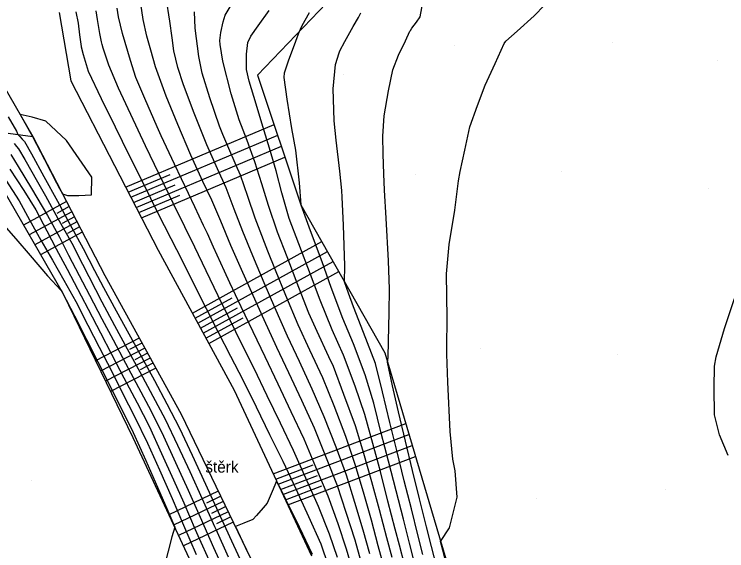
# Model space of a CAD drawing. Extents: x -448957 to -448612, y -1107690 to -1107245.
# Drawn here: x -448752.23 to -448714.86, y -1107411.41 to -1107383.27 of the extents above; entities that cross this region are included whole.
import ezdxf

# ---------------------------------------------------------------- set-up
doc = ezdxf.new("R2010")
doc.units = 0
for name, color, linetype in [('Default', 7, 'Continuous'), ('Vrstva 1', 7, 'Continuous'), ('Vrstva 11', 7, 'Continuous'), ('Vrstva 14', 7, 'Continuous'), ('Vrstva 15', 7, 'Continuous'), ('Vrstva 16', 7, 'Continuous'), ('Vrstva 17', 7, 'Continuous'), ('Vrstva 40', 7, 'Continuous')]:
    doc.layers.add(name, color=color, linetype=linetype)

# ---------------------------------------------------------------- blocks, each defined once
blk = doc.blocks.new('POINT_DISPLAY')
at = {"layer": 'Default'}
blk.add_line((0, 0), (0, 0), dxfattribs=at)

msp = doc.modelspace()

# ---------------------------------------------------------------- linework, layer by layer
at = {"layer": 'Vrstva 11'}
for p, q in [((-448749.871, -1107383.186), (-448749.267, -1107386.764)), ((-448753.87, -1107385.167), (-448751.25, -1107389.68)), ((-448749.267, -1107386.764), (-448744.681, -1107395.638)), ((-448751.25, -1107389.68), (-448747.484, -1107396.982)), ((-448744.681, -1107395.638), (-448740.7, -1107402.99)), ((-448747.484, -1107396.982), (-448743.482, -1107404.246)), ((-448740.7, -1107402.99), (-448736.632, -1107411.673)), ((-448743.482, -1107404.246), (-448739.337, -1107412.816))]:
    msp.add_line(p, q, dxfattribs=at)
at = {"layer": 'Vrstva 14'}
for p, q in [((-448735.861, -1107382.696), (-448739.463, -1107386.469)), ((-448739.463, -1107386.469), (-448737.194, -1107393.26)), ((-448752.54, -1107389.502), (-448751.25, -1107389.68)), ((-448753.315, -1107391.608), (-448749.664, -1107397.93)), ((-448737.194, -1107393.26), (-448732.795, -1107401.025)), ((-448749.664, -1107397.93), (-448746.015, -1107405.477)), ((-448732.795, -1107401.025), (-448730.205, -1107409.781)), ((-448746.015, -1107405.477), (-448742.15, -1107413.742)), ((-448730.205, -1107409.781), (-448728.39, -1107415.928))]:
    msp.add_line(p, q, dxfattribs=at)
at = {"layer": 'Vrstva 15'}
for p, q in [((-448746.386, -1107392.338), (-448738.601, -1107389.049)), ((-448746.11, -1107392.873), (-448738.41, -1107389.62)), ((-448745.834, -1107393.408), (-448738.219, -1107390.191)), ((-448745.557, -1107393.942), (-448738.029, -1107390.762)), ((-448746.248, -1107392.606), (-448744.048, -1107391.676)), ((-448745.972, -1107393.14), (-448743.796, -1107392.221)), ((-448745.695, -1107393.675), (-448743.544, -1107392.766)), ((-448749.487, -1107393.098), (-448751.743, -1107394.33)), ((-448749.35, -1107393.364), (-448749.994, -1107393.716)), ((-448749.212, -1107393.631), (-448751.443, -1107394.849)), ((-448749.075, -1107393.898), (-448749.712, -1107394.246)), ((-448748.937, -1107394.164), (-448751.143, -1107395.369)), ((-448748.8, -1107394.431), (-448749.43, -1107394.775)), ((-448748.662, -1107394.698), (-448750.843, -1107395.889)), ((-448742.887, -1107398.952), (-448736.1, -1107395.192)), ((-448742.601, -1107399.479), (-448735.804, -1107395.714)), ((-448742.315, -1107400.007), (-448735.508, -1107396.236)), ((-448742.03, -1107400.534), (-448735.212, -1107396.758)), ((-448742.744, -1107399.215), (-448740.802, -1107398.14)), ((-448742.458, -1107399.743), (-448740.513, -1107398.666)), ((-448742.172, -1107400.271), (-448740.225, -1107399.192)), ((-448745.676, -1107400.263), (-448747.964, -1107401.446)), ((-448745.531, -1107400.526), (-448746.185, -1107400.864)), ((-448745.387, -1107400.789), (-448747.703, -1107401.986)), ((-448745.097, -1107401.315), (-448747.442, -1107402.526)), ((-448745.242, -1107401.052), (-448745.904, -1107401.394)), ((-448744.952, -1107401.578), (-448745.622, -1107401.924)), ((-448744.807, -1107401.84), (-448747.18, -1107403.067)), ((-448738.645, -1107407.377), (-448731.696, -1107404.739)), ((-448738.389, -1107407.922), (-448731.526, -1107405.316)), ((-448738.134, -1107408.467), (-448731.355, -1107405.893)), ((-448737.879, -1107409.012), (-448731.184, -1107406.47)), ((-448738.517, -1107407.65), (-448736.556, -1107406.905)), ((-448738.262, -1107408.194), (-448736.325, -1107407.459)), ((-448738.006, -1107408.739), (-448736.094, -1107408.013)), ((-448741.527, -1107408.289), (-448744.123, -1107409.524)), ((-448741.265, -1107408.829), (-448743.868, -1107410.067)), ((-448741.396, -1107408.559), (-448742.138, -1107408.912)), ((-448741.135, -1107409.099), (-448741.878, -1107409.453)), ((-448741.004, -1107409.369), (-448743.614, -1107410.611)), ((-448740.743, -1107409.909), (-448743.36, -1107411.154)), ((-448740.873, -1107409.639), (-448741.619, -1107409.994))]:
    msp.add_line(p, q, dxfattribs=at)
at = {"layer": 'Vrstva 16'}
for points in [[(-448734.507, -1107412.352), (-448734.804, -1107411.331), (-448735.241, -1107410.005), (-448735.762, -1107408.559), (-448736.409, -1107407.026), (-448737.025, -1107405.563), (-448737.707, -1107404.126), (-448738.39, -1107402.68), (-448739.074, -1107401.249), (-448739.704, -1107399.937), (-448740.333, -1107398.615), (-448740.921, -1107397.365), (-448741.204, -1107396.749), (-448741.775, -1107395.494), (-448742.1, -1107394.768), (-448742.296, -1107394.349), (-448742.763, -1107393.373), (-448743.096, -1107392.679), (-448743.825, -1107391.138), (-448744.523, -1107389.657), (-448744.735, -1107389.179), (-448745.38, -1107387.697), (-448745.849, -1107386.584), (-448746.126, -1107385.705), (-448746.547, -1107384.28), (-448746.763, -1107383.405), (-448746.835, -1107382.953)], [(-448731.763, -1107412.142), (-448732.03, -1107411.112), (-448732.244, -1107410.281), (-448732.628, -1107408.808), (-448733.028, -1107407.262), (-448733.43, -1107405.793), (-448733.839, -1107404.271), (-448734.352, -1107402.789), (-448734.962, -1107401.155), (-448735.548, -1107399.824), (-448736.19, -1107398.278), (-448736.694, -1107396.926), (-448737.309, -1107395.307), (-448737.805, -1107393.981), (-448738.189, -1107392.641), (-448738.49, -1107391.484), (-448738.834, -1107390.294), (-448739.184, -1107389.153), (-448739.546, -1107387.993), (-448739.903, -1107386.777), (-448740.047, -1107386.171), (-448740.049, -1107385.374), (-448739.978, -1107384.754), (-448739.822, -1107384.425), (-448739.433, -1107383.881), (-448738.852, -1107383.068)], [(-448752.407, -1107390.621), (-448752.021, -1107391.261), (-448751.318, -1107392.407), (-448750.478, -1107393.82), (-448749.85, -1107394.973), (-448749.377, -1107395.902), (-448748.816, -1107396.977), (-448748.277, -1107398.001), (-448747.629, -1107399.241), (-448747.047, -1107400.352), (-448746.391, -1107401.575), (-448745.715, -1107402.842), (-448745.072, -1107404.065), (-448744.404, -1107405.406), (-448743.766, -1107406.787), (-448743.113, -1107408.229), (-448742.485, -1107409.65), (-448741.77, -1107411.251), (-448741.121, -1107412.693)], [(-448714.797, -1107406.413), (-448715.24, -1107405.328), (-448715.513, -1107404.285), (-448715.528, -1107402.873), (-448715.506, -1107401.726), (-448715.424, -1107401.238), (-448714.977, -1107399.759), (-448714.452, -1107398.185)]]:
    msp.add_lwpolyline(points, dxfattribs=at)
at = {"layer": 'Vrstva 17'}
for points in [[(-448733.584, -1107411.573), (-448733.922, -1107410.334), (-448734.365, -1107408.878), (-448734.809, -1107407.451), (-448735.345, -1107405.984), (-448735.971, -1107404.394), (-448736.598, -1107402.934), (-448737.274, -1107401.482), (-448737.895, -1107400.16), (-448738.555, -1107398.662), (-448739.117, -1107397.36), (-448739.712, -1107395.946), (-448740.235, -1107394.676), (-448740.689, -1107393.492), (-448741.121, -1107392.377), (-448741.571, -1107391.372), (-448742.13, -1107390.126), (-448742.788, -1107388.459), (-448743.346, -1107386.974), (-448743.648, -1107386.068), (-448743.856, -1107385.186), (-448743.951, -1107384.517), (-448744.071, -1107383.633), (-448744.26, -1107382.388)], [(-448730.074, -1107412.274), (-448730.348, -1107411.198), (-448730.607, -1107410.162), (-448730.975, -1107408.684), (-448731.344, -1107407.206), (-448732.085, -1107404.133), (-448732.385, -1107402.761), (-448732.648, -1107401.522), (-448732.621, -1107401.269), (-448732.594, -1107400.426), (-448732.57, -1107398.909), (-448732.555, -1107397.684), (-448732.608, -1107396.21), (-448732.732, -1107393.966), (-448732.81, -1107392.499), (-448732.841, -1107391.647), (-448732.88, -1107390.617), (-448732.906, -1107389.663), (-448732.82, -1107388.6), (-448732.609, -1107387.282), (-448732.367, -1107386.179), (-448732.08, -1107385.419), (-448731.714, -1107384.662), (-448731.48, -1107384.164), (-448731.451, -1107384.124), (-448731.37, -1107384.005), (-448731.131, -1107383.695), (-448730.947, -1107383.409), (-448730.794, -1107382.647)], [(-448734.033, -1107411.994), (-448734.347, -1107410.865), (-448734.813, -1107409.415), (-448735.267, -1107408.017), (-448735.854, -1107406.55), (-448736.488, -1107404.979), (-448737.15, -1107403.528), (-448737.828, -1107402.079), (-448738.455, -1107400.759), (-448739.128, -1107399.299), (-448739.705, -1107398.027), (-448740.316, -1107396.657), (-448740.864, -1107395.395), (-448741.395, -1107394.13), (-448741.869, -1107393.029), (-448742.33, -1107392.042), (-448742.964, -1107390.666), (-448743.657, -1107389.06), (-448744.258, -1107387.576), (-448744.825, -1107386.027), (-448745.071, -1107385.147), (-448745.278, -1107384.421), (-448745.47, -1107383.539), (-448745.595, -1107382.733)], [(-448732.415, -1107411.759), (-448732.686, -1107410.73), (-448733.071, -1107409.273), (-448733.47, -1107407.804), (-448733.893, -1107406.32), (-448734.325, -1107404.853), (-448734.938, -1107403.225), (-448735.493, -1107401.748), (-448735.726, -1107401.243), (-448736.336, -1107399.918), (-448736.771, -1107398.948), (-448737.299, -1107397.602), (-448737.922, -1107396.003), (-448738.42, -1107394.705), (-448738.893, -1107393.303), (-448739.237, -1107392.16), (-448739.602, -1107391.006), (-448740.017, -1107389.886), (-448740.424, -1107388.805), (-448740.86, -1107387.446), (-448741.288, -1107385.735), (-448741.42, -1107384.852), (-448741.448, -1107384.642), (-448741.387, -1107384.233), (-448741.263, -1107383.664), (-448741.159, -1107383.321), (-448740.9, -1107382.883)], [(-448729.635, -1107411.863), (-448729.754, -1107411.382), (-448729.868, -1107410.922), (-448729.404, -1107410.219), (-448728.997, -1107408.604), (-448729.107, -1107407.219), (-448729.231, -1107406.603), (-448729.361, -1107405.15), (-448729.489, -1107402.573), (-448729.544, -1107401.099), (-448729.539, -1107400.752), (-448729.532, -1107399.205), (-448729.553, -1107396.891), (-448729.423, -1107395.348), (-448729.13, -1107393.554), (-448728.923, -1107392.017), (-448728.84, -1107391.528), (-448728.606, -1107390.4), (-448728.332, -1107389.184), (-448727.927, -1107388.052), (-448727.525, -1107386.99), (-448727.013, -1107385.855), (-448726.528, -1107384.805), (-448726.45, -1107384.68), (-448725.853, -1107384.166), (-448724.959, -1107383.349), (-448724.428, -1107382.793)], [(-448735.751, -1107412.198), (-448736.133, -1107411.074), (-448736.772, -1107409.632), (-448737.447, -1107408.178), (-448738.133, -1107406.733), (-448738.827, -1107405.329), (-448739.527, -1107403.887), (-448740.217, -1107402.473), (-448740.868, -1107401.221), (-448741.52, -1107399.963), (-448742.147, -1107398.726), (-448742.789, -1107397.443), (-448743.412, -1107396.205), (-448744.004, -1107395.047), (-448744.689, -1107393.686), (-448745.439, -1107392.182), (-448746.181, -1107390.702), (-448746.924, -1107389.186), (-448747.656, -1107387.706), (-448748.327, -1107386.274), (-448748.592, -1107385.405), (-448748.697, -1107384.993), (-448748.7, -1107384.966), (-448748.782, -1107384.355), (-448748.864, -1107383.741), (-448748.972, -1107383.15)], [(-448735.278, -1107411.764), (-448735.687, -1107410.539), (-448736.267, -1107409.095), (-448736.928, -1107407.602), (-448737.579, -1107406.148), (-448738.267, -1107404.727), (-448738.959, -1107403.284), (-448739.645, -1107401.861), (-448740.286, -1107400.579), (-448740.926, -1107399.289), (-448741.534, -1107398.046), (-448742.164, -1107396.728), (-448742.759, -1107395.481), (-448743.284, -1107394.419), (-448743.893, -1107393.182), (-448744.632, -1107391.66), (-448745.352, -1107390.179), (-448746.762, -1107387.145), (-448747.263, -1107385.937), (-448747.566, -1107385.059), (-448747.624, -1107384.865), (-448747.659, -1107384.719), (-448747.736, -1107384.274), (-448747.855, -1107383.554), (-448747.925, -1107383.1)], [(-448732.859, -1107412.178), (-448733.135, -1107411.152), (-448733.497, -1107409.804), (-448733.917, -1107408.341), (-448734.351, -1107406.886), (-448734.835, -1107405.419), (-448735.455, -1107403.81), (-448736.045, -1107402.341), (-448736.72, -1107400.885), (-448737.336, -1107399.561), (-448737.981, -1107398.024), (-448738.528, -1107396.692), (-448738.924, -1107395.706), (-448739.424, -1107394.429), (-448739.596, -1107393.965), (-448739.984, -1107392.836), (-448740.37, -1107391.719), (-448740.59, -1107391.206), (-448741.034, -1107390.19), (-448741.297, -1107389.586), (-448741.46, -1107389.145), (-448741.973, -1107387.659), (-448742.376, -1107386.363), (-448742.544, -1107385.48), (-448742.741, -1107384.008), (-448742.778, -1107383.14)], [(-448731.236, -1107412.039), (-448731.501, -1107411.008), (-448731.821, -1107409.749), (-448732.2, -1107408.274), (-448732.595, -1107406.712), (-448732.981, -1107405.24), (-448733.374, -1107403.673), (-448733.82, -1107402.187), (-448734.434, -1107400.562), (-448734.991, -1107399.224), (-448735.609, -1107397.608), (-448736.088, -1107396.25), (-448736.691, -1107394.624), (-448737.182, -1107393.282), (-448737.183, -1107393.269), (-448737.274, -1107392.113), (-448737.463, -1107390.399), (-448737.666, -1107389.265), (-448737.909, -1107387.719), (-448738.077, -1107386.585), (-448738.061, -1107386.349), (-448737.837, -1107385.723), (-448737.46, -1107384.686), (-448737.264, -1107384.166), (-448737.216, -1107384.049), (-448737.124, -1107383.86), (-448736.744, -1107383.187)], [(-448730.792, -1107411.618), (-448731.054, -1107410.585), (-448731.398, -1107409.216), (-448731.772, -1107407.74), (-448732.161, -1107406.163), (-448732.533, -1107404.686), (-448732.91, -1107403.075), (-448733.289, -1107401.585), (-448733.906, -1107399.969), (-448734.435, -1107398.624), (-448734.698, -1107397.902), (-448734.901, -1107397.308), (-448734.893, -1107396.467), (-448734.955, -1107394.334), (-448735.031, -1107392.866), (-448735.056, -1107392.519), (-448735.157, -1107391.506), (-448735.34, -1107389.877), (-448735.449, -1107388.865), (-448735.462, -1107388.291), (-448735.496, -1107387.189), (-448735.375, -1107385.907), (-448735.196, -1107385.299), (-448735.155, -1107385.185), (-448734.887, -1107384.699), (-448734.45, -1107383.922), (-448734.18, -1107383.437), (-448734.057, -1107383.198)], [(-448752.552, -1107388.661), (-448752.118, -1107389.413), (-448752.032, -1107389.572), (-448751.943, -1107389.677), (-448751.814, -1107389.829), (-448751.697, -1107389.95), (-448751.33, -1107390.588), (-448750.68, -1107391.784), (-448749.963, -1107393.084), (-448749.311, -1107394.278), (-448748.62, -1107395.554), (-448748.015, -1107396.711), (-448747.549, -1107397.609), (-448746.884, -1107398.829), (-448746.217, -1107400.038), (-448745.552, -1107401.25), (-448744.881, -1107402.486), (-448744.225, -1107403.701), (-448743.566, -1107404.99), (-448742.903, -1107406.4), (-448742.198, -1107407.928), (-448741.539, -1107409.367), (-448740.835, -1107410.893), (-448740.17, -1107412.33)], [(-448749.428, -1107392.781), (-448748.844, -1107392.783), (-448748.177, -1107392.741), (-448748.165, -1107391.819), (-448749.49, -1107389.891), (-448750.567, -1107388.872), (-448751.287, -1107388.674), (-448751.915, -1107388.535), (-448751.267, -1107389.678), (-448751.262, -1107389.682), (-448750.639, -1107390.889), (-448750.011, -1107392.106), (-448749.85, -1107392.406), (-448749.698, -1107392.69), (-448749.428, -1107392.781)], [(-448752.238, -1107390.06), (-448752.111, -1107390.208), (-448752.002, -1107390.337), (-448751.676, -1107390.893), (-448751.004, -1107392.069), (-448750.592, -1107392.798), (-448749.933, -1107393.985), (-448749.214, -1107395.287), (-448748.65, -1107396.387), (-448747.626, -1107398.359), (-448746.97, -1107399.593), (-448746.3, -1107400.82), (-448745.638, -1107402.033), (-448744.961, -1107403.3), (-448744.312, -1107404.519), (-448743.666, -1107405.881), (-448743.018, -1107407.263), (-448742.374, -1107408.691), (-448741.726, -1107410.134), (-448741.658, -1107410.285), (-448741.001, -1107411.725)], [(-448752.466, -1107391.394), (-448751.729, -1107392.509), (-448751.09, -1107393.532), (-448750.511, -1107394.633), (-448750.028, -1107395.571), (-448749.452, -1107396.639), (-448748.346, -1107398.739), (-448747.706, -1107399.983), (-448747.121, -1107401.108), (-448746.473, -1107402.345), (-448745.788, -1107403.66), (-448745.153, -1107404.887), (-448744.498, -1107406.307), (-448743.868, -1107407.692), (-448743.338, -1107408.905), (-448742.732, -1107410.302), (-448742.597, -1107410.613), (-448741.954, -1107412.056)], [(-448752.677, -1107391.98), (-448751.975, -1107393.051), (-448751.422, -1107394.053), (-448750.834, -1107395.115), (-448750.228, -1107396.166), (-448749.625, -1107397.222), (-448749.004, -1107398.338), (-448748.366, -1107399.583), (-448747.776, -1107400.738), (-448747.136, -1107401.982), (-448746.544, -1107403.144), (-448745.917, -1107404.38), (-448745.239, -1107405.775), (-448744.616, -1107407.163), (-448743.954, -1107408.668), (-448743.354, -1107410.067), (-448742.687, -1107411.611)], [(-448753.168, -1107393.902), (-448752.149, -1107395.05), (-448751.401, -1107395.934), (-448750.479, -1107396.989), (-448749.759, -1107397.766), (-448749.71, -1107397.847), (-448749.072, -1107399.084), (-448748.437, -1107400.33), (-448747.844, -1107401.497), (-448747.21, -1107402.743), (-448745.991, -1107405.211), (-448745.326, -1107406.683), (-448744.71, -1107408.074), (-448744.234, -1107409.191), (-448743.814, -1107410.184), (-448743.957, -1107410.69), (-448744.341, -1107412.183), (-448744.778, -1107413.902), (-448745.203, -1107415.494), (-448745.497, -1107416.608), (-448745.747, -1107417.444), (-448746.06, -1107418.563), (-448746.271, -1107419.421), (-448746.351, -1107419.743)], [(-448736.579, -1107411.609), (-448737.276, -1107410.168), (-448737.966, -1107408.755), (-448738.22, -1107408.247), (-448738.467, -1107407.755), (-448738.699, -1107408.313), (-448738.957, -1107408.915), (-448739.174, -1107409.159), (-448739.527, -1107409.557), (-448739.723, -1107409.781), (-448740.194, -1107409.972), (-448740.633, -1107410.136), (-448740.003, -1107411.482)]]:
    msp.add_lwpolyline(points, dxfattribs=at)

# ---------------------------------------------------------------- block references
at = {"layer": 'Vrstva 1', "xscale": 0.1, "yscale": 0.10000000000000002}
for p in [(-448749.267, -1107386.764), (-448739.463, -1107386.469), (-448751.25, -1107389.68), (-448751.25, -1107389.68), (-448737.194, -1107393.26), (-448744.681, -1107395.638), (-448747.484, -1107396.982), (-448749.664, -1107397.93), (-448732.795, -1107401.025), (-448740.7, -1107402.99), (-448743.482, -1107404.246), (-448746.015, -1107405.477), (-448730.205, -1107409.781)]:
    msp.add_blockref('POINT_DISPLAY', p, dxfattribs=at)
at = {"layer": 'Vrstva 14', "xscale": 0.1, "yscale": 0.10000000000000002}
for p in [(-448729.135, -1107384.895), (-448720.866, -1107384.741), (-448715.363, -1107385.675), (-448734.974, -1107386.43), (-448723.536, -1107391.545), (-448731.206, -1107391.679), (-448715.823, -1107392.424), (-448727.764, -1107400.819), (-448720.587, -1107401.137), (-448751.342, -1107407.739), (-448718.093, -1107408.223), (-448724.816, -1107408.655)]:
    msp.add_blockref('POINT_DISPLAY', p, dxfattribs=at)

# ---------------------------------------------------------------- texts
at = {"layer": 'Vrstva 40'}
msp.add_text('štěrk', height=0.6, dxfattribs=at).set_placement((-448742.207, -1107407.314))

doc.saveas('drawing.dxf')
